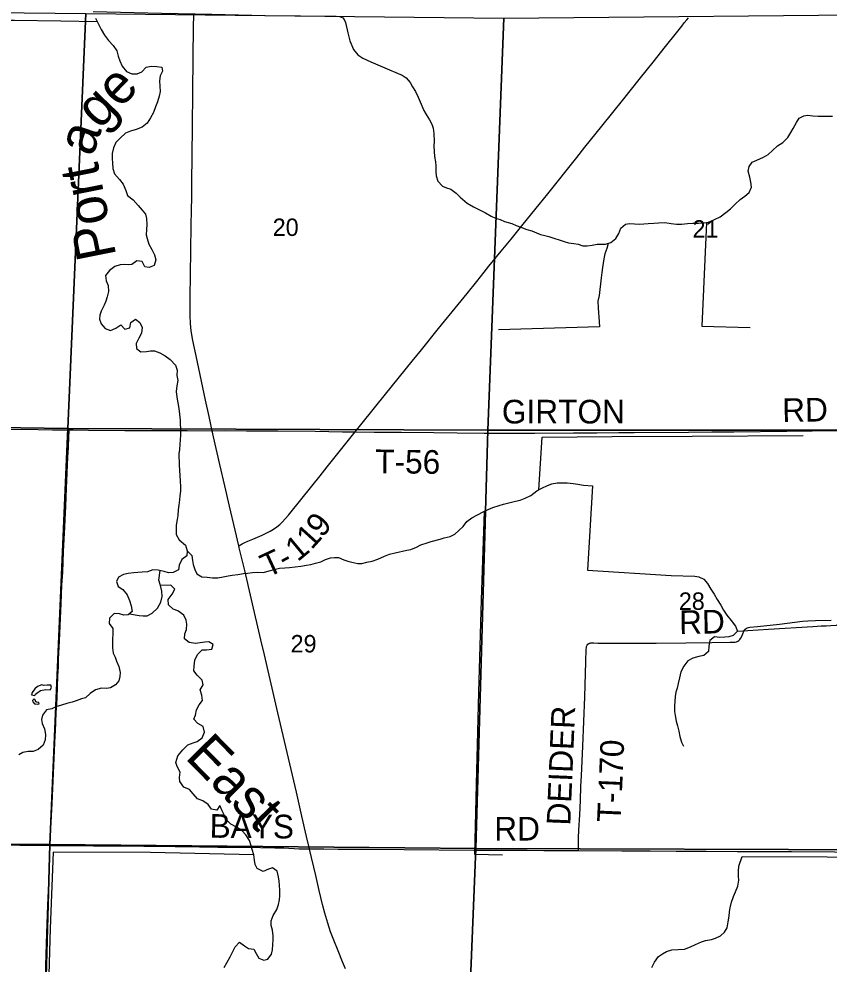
# Model space of a CAD drawing. Extents: x 1443599 to 1910620, y 1028088 to 1361369.
# Drawn here: x 1688678 to 1698953, y 1190596 to 1202581 of the extents above; entities that cross this region are included whole.
import ezdxf

# ---------------------------------------------------------------- set-up
doc = ezdxf.new("R2010")
doc.units = 0
for name, color, linetype in [('GM_X_Major_River', 7, 'Continuous'), ('GM_X_Major_River_Text', 7, 'Continuous'), ('GM_X_Minor_Lake', 7, 'Continuous'), ('GM_X_Minor_River', 7, 'Continuous'), ('GM_X_Section', 7, 'Continuous'), ('GM_X_Section_Text', 7, 'Continuous'), ('GM_X_State_Route', 7, 'Continuous'), ('GM_X_Township_Road', 7, 'Continuous'), ('GM_X_Township_Road_Text', 7, 'Continuous')]:
    doc.layers.add(name, color=color, linetype=linetype)

msp = doc.modelspace()

# ---------------------------------------------------------------- linework, layer by layer
at = {"layer": 'GM_X_Major_River'}
for points in [[(1689649, 1202592), (1689687, 1202516), (1689722, 1202449), (1689765, 1202376), (1689812, 1202309), (1689873, 1202243), (1689918, 1202178), (1689937, 1202110), (1689958, 1202051), (1689989, 1201983), (1690042, 1201914), (1690111, 1201886), (1690178, 1201885), (1690238, 1201910), (1690292, 1201969), (1690354, 1201982), (1690426, 1201977), (1690492, 1201970), (1690501, 1201919), (1690470, 1201858), (1690461, 1201796), (1690466, 1201727), (1690469, 1201661), (1690455, 1201601), (1690434, 1201531), (1690411, 1201466), (1690383, 1201394), (1690348, 1201328), (1690303, 1201261), (1690242, 1201208), (1690165, 1201181), (1690094, 1201158), (1690030, 1201134), (1689962, 1201071), (1689905, 1201013), (1689876, 1200948), (1689860, 1200876), (1689861, 1200808), (1689864, 1200755), (1689869, 1200685), (1689892, 1200615), (1689953, 1200543), (1690002, 1200484), (1690033, 1200407), (1690057, 1200341), (1690125, 1200285), (1690192, 1200216), (1690241, 1200155), (1690282, 1200104), (1690297, 1200050), (1690302, 1199975), (1690298, 1199911), (1690293, 1199845), (1690304, 1199795), (1690327, 1199724), (1690362, 1199659), (1690397, 1199591), (1690416, 1199526), (1690393, 1199454), (1690330, 1199429), (1690276, 1199438), (1690241, 1199503), (1690175, 1199512), (1690112, 1199465), (1690062, 1199462), (1690012, 1199467), (1689961, 1199464), (1689893, 1199441), (1689826, 1199392), (1689776, 1199327), (1689785, 1199261), (1689808, 1199202), (1689813, 1199124), (1689799, 1199056), (1689780, 1199004), (1689759, 1198952), (1689722, 1198877), (1689705, 1198825), (1689700, 1198775), (1689721, 1198714), (1689770, 1198657), (1689840, 1198632), (1689905, 1198659), (1689972, 1198704), (1690021, 1198649), (1690083, 1198662), (1690099, 1198730), (1690158, 1198773)], [(1690158, 1198773), (1690213, 1198731), (1690242, 1198667), (1690231, 1198597), (1690197, 1198535), (1690166, 1198466), (1690169, 1198401), (1690226, 1198360), (1690295, 1198363), (1690345, 1198372), (1690397, 1198371), (1690467, 1198346), (1690532, 1198311), (1690598, 1198263), (1690663, 1198192), (1690686, 1198129), (1690680, 1198059), (1690693, 1197995), (1690680, 1197927), (1690673, 1197857), (1690681, 1197784), (1690694, 1197714), (1690705, 1197642), (1690716, 1197571), (1690724, 1197495), (1690725, 1197443), (1690726, 1197386), (1690727, 1197308), (1690724, 1197238), (1690719, 1197188), (1690714, 1197120), (1690707, 1197066), (1690712, 1196925), (1690713, 1196853), (1690718, 1196791), (1690722, 1196721), (1690729, 1196650), (1690726, 1196594), (1690717, 1196532), (1690714, 1196482), (1690705, 1196414), (1690698, 1196358), (1690693, 1196286), (1690686, 1196234), (1690674, 1196162), (1690673, 1196110), (1690674, 1196044), (1690709, 1195977), (1690792, 1195906), (1690813, 1195836)], [(1690813, 1195836), (1690808, 1195774), (1690743, 1195725), (1690711, 1195656), (1690700, 1195596), (1690635, 1195561), (1690573, 1195558), (1690521, 1195573), (1690445, 1195592), (1690375, 1195594), (1690310, 1195571), (1690242, 1195564), (1690186, 1195563), (1690136, 1195556), (1690065, 1195549), (1690005, 1195538), (1689940, 1195501), (1689917, 1195449), (1689936, 1195385), (1689997, 1195346), (1690050, 1195277), (1690079, 1195206), (1690100, 1195137), (1690113, 1195069), (1690062, 1195024), (1690008, 1195021), (1689954, 1195036), (1689884, 1195043), (1689826, 1194982), (1689823, 1194916), (1689870, 1194853), (1689869, 1194784), (1689866, 1194716), (1689863, 1194660), (1689866, 1194608), (1689874, 1194538)], [(1690079, 1195038), (1690202, 1195015), (1690252, 1195012), (1690306, 1195011), (1690369, 1195044), (1690437, 1195109), (1690476, 1195185), (1690493, 1195257), (1690489, 1195323), (1690474, 1195395), (1690453, 1195466), (1690470, 1195586)], [(1691701, 1191807), (1691676, 1191860), (1691665, 1191912), (1691656, 1191982), (1691637, 1192047), (1691624, 1192097), (1691603, 1192162), (1691557, 1192233), (1691503, 1192290), (1691436, 1192333), (1691366, 1192371), (1691313, 1192420), (1691288, 1192472), (1691257, 1192541), (1691224, 1192606), (1691187, 1192548), (1691121, 1192560), (1691080, 1192620), (1691012, 1192664), (1690943, 1192691), (1690886, 1192756), (1690843, 1192809), (1690771, 1192841), (1690718, 1192912), (1690715, 1192962), (1690722, 1193030), (1690687, 1193101), (1690666, 1193153), (1690694, 1193235), (1690755, 1193312), (1690821, 1193377), (1690887, 1193402), (1690938, 1193419), (1691001, 1193464), (1691030, 1193536), (1691013, 1193608), (1690946, 1193648), (1690895, 1193701), (1690916, 1193753), (1690931, 1193819), (1690966, 1193882), (1691007, 1193938), (1690999, 1194006), (1690978, 1194074), (1691015, 1194136), (1691002, 1194198), (1690937, 1194260), (1690898, 1194315), (1690899, 1194375), (1690910, 1194451), (1690944, 1194522), (1691003, 1194579), (1691059, 1194580), (1691125, 1194589), (1691141, 1194649), (1691087, 1194682), (1691035, 1194679), (1690978, 1194670), (1690916, 1194663), (1690836, 1194673), (1690777, 1194720), (1690782, 1194784), (1690805, 1194840), (1690808, 1194906), (1690801, 1194958), (1690768, 1195019), (1690693, 1195074), (1690633, 1195098), (1690574, 1195153), (1690569, 1195219), (1690622, 1195286), (1690656, 1195352), (1690604, 1195399), (1690474, 1195395)], [(1689874, 1194538), (1689898, 1194487), (1689917, 1194436), (1689946, 1194368), (1689962, 1194293), (1689957, 1194243), (1689944, 1194189), (1689903, 1194138), (1689839, 1194101), (1689788, 1194090), (1689724, 1194093), (1689651, 1194074), (1689580, 1194025), (1689521, 1193972), (1689471, 1193961), (1689404, 1193932), (1689354, 1193917), (1689287, 1193900), (1689217, 1193881), (1689146, 1193857), (1689095, 1193831), (1689027, 1193819), (1688977, 1193751), (1688964, 1193697), (1688974, 1193647), (1689002, 1193578), (1689015, 1193508), (1689012, 1193440), (1688985, 1193370), (1688924, 1193317), (1688857, 1193292), (1688795, 1193291), (1688726, 1193280), (1688676, 1193251)], [(1691283, 1190553), (1691321, 1190622), (1691358, 1190686), (1691394, 1190762), (1691421, 1190813), (1691476, 1190872), (1691539, 1190829), (1691591, 1190794), (1691659, 1190787), (1691686, 1190732), (1691719, 1190671), (1691783, 1190646), (1691833, 1190657), (1691880, 1190721), (1691893, 1190777), (1691899, 1190845), (1691902, 1190903), (1691903, 1190953), (1691892, 1191025), (1691879, 1191084), (1691876, 1191146), (1691903, 1191214), (1691947, 1191289), (1691972, 1191353), (1691981, 1191409), (1691986, 1191463), (1691989, 1191529), (1691984, 1191595), (1691977, 1191646), (1691968, 1191704), (1691954, 1191774), (1691894, 1191818), (1691844, 1191798), (1691775, 1191772), (1691701, 1191807)]]:
    msp.add_lwpolyline(points, dxfattribs=at)
at = {"layer": 'GM_X_Minor_Lake'}
for p, q in [((1688996, 1194128), (1688968, 1194137)), ((1688874, 1193896), (1688888, 1193895))]:
    msp.add_line(p, q, dxfattribs=at)
for points in [[(1688968, 1194137), (1688914, 1194114), (1688881, 1194086), (1688848, 1194038), (1688838, 1194011), (1688880, 1194002), (1688890, 1194018), (1688906, 1194033), (1688951, 1194067), (1689019, 1194076), (1689074, 1194075), (1689092, 1194102), (1689081, 1194133), (1689037, 1194131), (1688996, 1194128)], [(1688888, 1193895), (1688914, 1193893), (1688936, 1193894), (1688930, 1193915), (1688904, 1193919), (1688894, 1193923), (1688885, 1193946), (1688873, 1193958), (1688852, 1193938), (1688854, 1193920), (1688874, 1193896)]]:
    msp.add_lwpolyline(points, dxfattribs=at)
at = {"layer": 'GM_X_Minor_River'}
for points in [[(1689618, 1202675), (1690487, 1202655), (1691124, 1202642), (1691800, 1202625), (1692702, 1202615), (1692745, 1202610), (1692786, 1202595), (1692802, 1202575), (1692821, 1202535), (1692849, 1202404), (1692875, 1202305), (1692923, 1202192), (1692976, 1202127), (1693039, 1202083), (1693141, 1202037), (1693348, 1201947), (1693489, 1201887), (1693537, 1201866), (1693587, 1201833)], [(1689672, 1202546), (1689211, 1202552), (1688623, 1202561), (1688118, 1202562), (1687412, 1202577), (1686863, 1202577), (1686812, 1201569), (1686787, 1200886), (1686768, 1200303), (1686738, 1199647), (1686720, 1199014), (1686707, 1198527), (1686694, 1197925), (1686666, 1197314), (1686650, 1196683)], [(1693587, 1201833), (1693640, 1201774), (1693669, 1201722), (1693706, 1201661), (1693741, 1201588), (1693766, 1201528), (1693813, 1201419), (1693844, 1201368), (1693887, 1201301), (1693914, 1201247), (1693930, 1201196), (1693941, 1201130), (1693943, 1201026), (1693942, 1200970), (1693945, 1200901), (1693948, 1200835), (1693959, 1200769), (1693964, 1200719), (1693967, 1200646), (1693968, 1200590), (1693989, 1200524), (1694048, 1200461), (1694102, 1200438), (1694154, 1200423), (1694222, 1200372), (1694273, 1200319), (1694362, 1200245), (1694441, 1200200), (1694519, 1200161), (1694597, 1200121), (1694666, 1200080), (1694724, 1200055), (1694780, 1200038), (1694838, 1200013), (1694931, 1199986), (1694985, 1199963), (1695045, 1199942), (1695119, 1199911), (1695183, 1199896), (1695242, 1199869), (1695294, 1199848), (1695346, 1199833), (1695400, 1199822), (1695462, 1199801), (1695540, 1199774), (1695592, 1199759), (1695648, 1199742), (1695716, 1199733), (1695772, 1199726), (1695829, 1199703), (1695884, 1199702), (1695950, 1199711), (1696012, 1199724), (1696064, 1199724), (1696117, 1199727), (1696183, 1199744), (1696248, 1199797), (1696287, 1199862), (1696310, 1199928), (1696369, 1199977), (1696423, 1199985), (1696486, 1199982), (1696550, 1199977), (1696604, 1199982), (1696660, 1199987), (1696730, 1199990), (1696791, 1199995), (1696871, 1199998), (1696951, 1199988), (1697019, 1199979), (1697079, 1199980), (1697155, 1199985), (1697224, 1199990), (1697298, 1199991), (1697368, 1199996), (1697422, 1200005), (1697501, 1200038), (1697572, 1200071), (1697645, 1200126), (1697704, 1200173), (1697763, 1200234), (1697826, 1200290), (1697883, 1200333), (1697938, 1200380), (1697969, 1200448), (1697962, 1200512), (1697949, 1200576), (1697928, 1200649), (1697937, 1200711), (1697976, 1200764), (1698036, 1200792), (1698119, 1200826), (1698182, 1200862), (1698235, 1200911), (1698300, 1200970), (1698365, 1201013), (1698430, 1201078), (1698469, 1201142), (1698498, 1201193), (1698539, 1201269), (1698574, 1201323)], [(1698574, 1201323), (1698633, 1201354), (1698683, 1201359), (1698747, 1201354), (1698813, 1201349), (1698879, 1201347), (1698942, 1201349), (1698995, 1201347)], [(1697399, 1200001), (1697340, 1198687), (1697951, 1198670)], [(1696151, 1199735), (1696134, 1199670), (1696109, 1199603), (1696094, 1199541), (1696087, 1199485), (1696080, 1199427), (1696071, 1199367), (1696062, 1199298), (1696053, 1199224), (1696045, 1199150), (1696036, 1199076), (1696019, 1199004), (1696022, 1198918), (1696027, 1198856), (1696034, 1198804), (1696039, 1198675)], [(1696039, 1198675), (1694760, 1198639)], [(1695271, 1196611), (1695312, 1197277), (1696203, 1197285), (1697218, 1197289), (1698624, 1197300)], [(1693448, 1195809), (1693596, 1195844), (1693650, 1195855), (1693719, 1195882), (1693775, 1195911), (1693856, 1195938), (1693908, 1195955), (1694021, 1195986), (1694073, 1195999), (1694146, 1196020), (1694206, 1196049), (1694259, 1196092), (1694312, 1196146), (1694357, 1196207), (1694422, 1196254), (1694493, 1196291), (1694566, 1196330), (1694628, 1196359), (1694687, 1196384), (1694768, 1196413), (1694824, 1196426), (1694907, 1196449), (1694975, 1196466), (1695033, 1196479), (1695098, 1196504), (1695169, 1196537), (1695246, 1196598), (1695310, 1196631), (1695383, 1196666), (1695438, 1196684), (1695506, 1196697), (1695562, 1196698), (1695632, 1196697), (1695706, 1196691), (1695766, 1196680), (1695840, 1196669), (1695953, 1196661)], [(1695953, 1196661), (1695890, 1195590), (1696950, 1195525), (1697248, 1195514)], [(1694580, 1196337), (1694542, 1195216), (1694508, 1194043), (1694476, 1192879), (1694454, 1191991), (1694811, 1191981)], [(1690813, 1195836), (1690870, 1195777), (1690881, 1195713), (1690888, 1195663), (1690907, 1195598), (1690936, 1195546), (1690997, 1195506), (1691065, 1195501), (1691131, 1195492), (1691202, 1195493), (1691268, 1195507), (1691330, 1195518), (1691383, 1195527), (1691453, 1195538), (1691526, 1195549), (1691576, 1195552), (1691640, 1195561), (1691708, 1195564), (1691779, 1195562), (1691851, 1195581), (1691914, 1195600), (1691984, 1195615), (1692052, 1195621), (1692111, 1195626), (1692183, 1195635), (1692253, 1195642), (1692326, 1195653), (1692380, 1195664), (1692439, 1195681), (1692505, 1195697), (1692568, 1195728), (1692629, 1195749), (1692681, 1195752), (1692733, 1195751), (1692797, 1195724), (1692850, 1195705), (1692902, 1195692), (1692974, 1195677), (1693026, 1195676), (1693091, 1195691), (1693159, 1195706), (1693228, 1195732), (1693313, 1195767), (1693377, 1195792), (1693448, 1195809)], [(1697248, 1195514), (1697300, 1195506), (1697362, 1195477), (1697409, 1195420), (1697452, 1195349), (1697495, 1195286), (1697534, 1195221), (1697579, 1195148), (1697612, 1195084), (1697654, 1195019), (1697711, 1194952), (1697766, 1194883), (1697791, 1194818), (1697736, 1194761), (1697679, 1194746), (1697629, 1194741), (1697569, 1194738), (1697501, 1194745), (1697442, 1194701), (1697429, 1194629), (1697424, 1194559), (1697365, 1194508), (1697301, 1194497), (1697226, 1194476), (1697163, 1194441), (1697112, 1194374), (1697073, 1194300), (1697054, 1194224), (1697037, 1194152), (1697026, 1194096), (1697011, 1194042), (1697002, 1193990), (1696997, 1193926), (1696992, 1193870), (1696993, 1193798), (1697002, 1193748), (1697013, 1193677), (1697028, 1193617), (1697045, 1193549), (1697060, 1193482), (1697081, 1193412), (1697108, 1193361)], [(1698746, 1194878), (1698802, 1194881), (1698853, 1194885), (1698915, 1194885), (1698975, 1194888), (1699047, 1194893), (1699120, 1194922), (1699187, 1194977), (1699228, 1195041), (1699243, 1195112), (1699312, 1195139), (1699384, 1195150), (1699446, 1195147), (1699507, 1195148), (1699559, 1195162), (1699615, 1195175), (1699665, 1195184), (1699734, 1195197)], [(1697791, 1194818), (1698186, 1194842), (1698746, 1194878)], [(1691656, 1191982), (1690348, 1192010), (1689111, 1192013), (1689073, 1191047), (1689055, 1190315), (1689024, 1189381), (1689004, 1188294), (1688989, 1187422)], [(1696706, 1190552), (1696739, 1190620), (1696790, 1190693), (1696841, 1190727), (1696891, 1190756), (1696960, 1190777), (1697117, 1190786), (1697193, 1190813), (1697260, 1190846), (1697333, 1190877), (1697387, 1190893), (1697461, 1190909), (1697512, 1190923), (1697576, 1190956), (1697627, 1191001), (1697658, 1191055), (1697673, 1191131), (1697685, 1191205), (1697689, 1191257), (1697696, 1191311), (1697713, 1191383), (1697739, 1191453), (1697765, 1191510), (1697795, 1191586), (1697810, 1191660), (1697805, 1191710), (1697802, 1191776), (1697809, 1191838), (1697851, 1191960)], [(1697851, 1191960), (1700006, 1191953), (1702413, 1191955), (1702411, 1191334), (1702395, 1190686), (1703522, 1190675), (1704942, 1190679)]]:
    msp.add_lwpolyline(points, dxfattribs=at)
at = {"layer": 'GM_X_Section'}
for points in [[(1684061, 1202709), (1689528, 1202650), (1689300, 1197389), (1683913, 1197462)], [(1689528, 1202650), (1694826, 1202591), (1694624, 1197366), (1689300, 1197389)], [(1694826, 1202591), (1700149, 1202640), (1699955, 1197367), (1694624, 1197366)], [(1689300, 1197389), (1689070, 1192111), (1683747, 1192150), (1683913, 1197462)], [(1694624, 1197366), (1694474, 1192060), (1689070, 1192111), (1689300, 1197389)], [(1694624, 1197366), (1699955, 1197367), (1699762, 1192045), (1694474, 1192060)], [(1683747, 1192150), (1689070, 1192111), (1688920, 1186781), (1683672, 1186813)], [(1689070, 1192111), (1694474, 1192060), (1694259, 1186758), (1689188, 1186776), (1688920, 1186781)], [(1694474, 1192060), (1699762, 1192045), (1699547, 1186749), (1694377, 1186759), (1694259, 1186758)]]:
    msp.add_lwpolyline(points, close=True, dxfattribs=at)
at = {"layer": 'GM_X_State_Route'}
for points in [[(1691130, 1197359), (1691090, 1197539), (1691045, 1197748), (1690924, 1198309), (1690885, 1198502), (1690867, 1198599), (1690858, 1198664), (1690853, 1198729), (1690851, 1198811), (1690851, 1198942), (1690851, 1199057), (1690854, 1199336), (1690864, 1199960), (1690866, 1200157), (1690869, 1200321), (1690871, 1200501), (1690879, 1201207), (1690885, 1201667), (1690894, 1202488), (1690898, 1202619), (1690898, 1202623)], [(1695277, 1200230), (1695385, 1200363), (1695754, 1200824), (1695856, 1200953), (1696072, 1201221), (1696349, 1201568), (1696544, 1201811), (1696740, 1202054), (1696861, 1202209), (1697035, 1202427), (1697086, 1202491), (1697116, 1202530), (1697147, 1202568), (1697169, 1202593)], [(1693666, 1198243), (1693782, 1198386), (1693999, 1198654), (1694247, 1198961), (1694361, 1199101), (1694486, 1199253), (1694578, 1199368), (1694639, 1199446), (1694795, 1199636), (1694919, 1199790), (1695074, 1199980), (1695277, 1200230)], [(1691569, 1197357), (1691960, 1197357), (1692436, 1197353), (1692781, 1197346), (1692942, 1197347), (1693029, 1197454), (1693329, 1197824), (1693666, 1198243)], [(1688281, 1197378), (1688922, 1197373), (1689102, 1197372), (1689318, 1197370), (1689365, 1197370), (1689562, 1197368), (1690022, 1197364), (1690531, 1197364), (1690570, 1197363)], [(1690570, 1197363), (1690810, 1197360), (1691130, 1197359)], [(1691130, 1197359), (1691139, 1197359), (1691303, 1197361), (1691566, 1197357), (1691569, 1197357)], [(1692820, 1190534), (1692783, 1190625), (1692726, 1190762), (1692671, 1190899), (1692631, 1191006), (1692595, 1191115), (1692558, 1191241), (1692529, 1191352), (1692487, 1191528), (1692442, 1191719), (1692365, 1192055), (1692364, 1192057), (1692327, 1192215), (1692268, 1192471), (1692198, 1192775), (1692096, 1193206), (1691963, 1193782), (1691851, 1194261), (1691791, 1194517), (1691746, 1194709), (1691627, 1195221), (1691541, 1195588), (1691473, 1195876), (1691467, 1195899), (1691421, 1196099), (1691350, 1196403), (1691291, 1196659), (1691228, 1196931), (1691147, 1197283), (1691130, 1197359)]]:
    msp.add_lwpolyline(points, dxfattribs=at)
at = {"layer": 'GM_X_Township_Road'}
for points in [[(1689168, 1194116), (1689168, 1194117), (1689173, 1194248), (1689178, 1194364), (1689182, 1194463), (1689192, 1194693), (1689213, 1195170), (1689224, 1195399), (1689233, 1195564), (1689245, 1195827), (1689259, 1196139), (1689272, 1196402), (1689281, 1196632), (1689300, 1197026), (1689306, 1197141), (1689313, 1197287), (1689317, 1197349), (1689318, 1197370)], [(1692942, 1197347), (1693185, 1197342), (1693529, 1197339), (1693940, 1197335), (1694235, 1197331), (1694579, 1197328), (1695219, 1197330), (1695711, 1197331), (1696007, 1197333), (1696285, 1197335), (1696482, 1197336), (1697171, 1197341), (1697467, 1197344), (1697745, 1197346), (1698418, 1197353), (1699058, 1197360), (1699452, 1197365), (1699796, 1197367), (1699942, 1197367)], [(1691467, 1195899), (1691508, 1195924), (1691541, 1195941), (1691579, 1195959), (1691643, 1195986), (1691763, 1196036), (1691823, 1196064), (1691866, 1196087), (1691907, 1196112), (1691947, 1196141), (1691985, 1196172), (1692020, 1196205), (1692053, 1196241), (1692096, 1196290), (1692271, 1196506), (1692497, 1196787), (1692589, 1196902), (1692721, 1197069), (1692942, 1197347)], [(1696356, 1194666), (1696760, 1194667), (1697137, 1194669), (1697466, 1194674), (1697696, 1194677), (1697745, 1194678), (1697761, 1194679), (1697778, 1194683), (1697794, 1194691), (1697807, 1194699), (1697820, 1194711), (1697831, 1194725), (1697840, 1194741), (1697846, 1194755), (1697857, 1194785), (1697870, 1194816), (1697877, 1194831), (1697887, 1194843), (1697900, 1194853), (1697915, 1194860), (1697930, 1194865), (1697947, 1194868), (1698045, 1194878), (1698322, 1194907), (1698616, 1194944), (1698681, 1194949), (1698780, 1194952), (1698977, 1194958)], [(1695773, 1192035), (1695774, 1192129), (1695775, 1192195), (1695779, 1192293), (1695790, 1192490), (1695798, 1192671), (1695805, 1192851), (1695811, 1192982), (1695828, 1193360), (1695853, 1193983), (1695869, 1194427), (1695872, 1194591), (1695874, 1194608), (1695878, 1194623), (1695885, 1194638), (1695894, 1194651), (1695907, 1194661), (1695914, 1194664), (1695922, 1194667), (1695930, 1194668), (1695939, 1194669), (1695955, 1194669), (1695971, 1194668), (1696020, 1194667), (1696168, 1194666), (1696333, 1194665), (1696356, 1194666)], [(1689138, 1193490), (1689141, 1193550), (1689151, 1193780), (1689158, 1193900), (1689162, 1193970), (1689168, 1194116)], [(1689073, 1192101), (1689084, 1192320), (1689100, 1192632), (1689124, 1193206), (1689133, 1193403), (1689138, 1193490)], [(1686943, 1192126), (1686981, 1192126), (1687211, 1192123), (1687572, 1192119), (1688048, 1192112), (1688409, 1192107), (1688688, 1192105), (1688967, 1192102), (1689073, 1192101)], [(1688935, 1187301), (1688934, 1187325), (1688934, 1187383), (1688937, 1187565), (1688943, 1187892), (1688949, 1188155), (1688953, 1188402), (1688958, 1188599), (1688967, 1188813), (1688977, 1189207), (1688989, 1189536), (1688999, 1189831), (1689011, 1190275), (1689025, 1190719), (1689034, 1190982), (1689046, 1191343), (1689056, 1191622), (1689069, 1192000), (1689072, 1192082), (1689073, 1192101)], [(1689073, 1192101), (1689296, 1192099), (1689624, 1192097), (1690264, 1192091), (1690658, 1192085), (1690970, 1192081), (1690975, 1192081)], [(1690975, 1192081), (1691200, 1192079), (1691498, 1192077)], [(1691498, 1192077), (1691561, 1192077), (1691922, 1192071), (1692037, 1192068), (1692234, 1192059), (1692349, 1192057), (1692364, 1192057)], [(1692364, 1192057), (1692546, 1192057), (1692726, 1192055), (1693120, 1192052), (1693564, 1192049), (1694449, 1192042), (1694450, 1192042), (1694664, 1192041), (1695123, 1192039), (1695337, 1192038), (1695649, 1192036), (1695773, 1192035)], [(1695773, 1192035), (1696323, 1192032), (1696685, 1192032), (1697014, 1192028), (1697145, 1192027), (1697392, 1192027), (1697787, 1192024), (1698099, 1192023), (1698477, 1192022), (1699020, 1192018), (1699365, 1192016), (1699661, 1192015), (1699747, 1192015)]]:
    msp.add_lwpolyline(points, dxfattribs=at)

# ---------------------------------------------------------------- texts
at = {"layer": 'GM_X_Major_River_Text'}
for s, height, rotation, p in [('ge', 500.3, 46.2354, (1689704, 1201167)), ('a', 500, 71.2343, (1689612, 1200824)), ('Port', 500.3, 101.2326, (1689915, 1199576)), ('East', 500.3, 314.5157, (1690773, 1193212))]:
    msp.add_text(s, height=height, rotation=rotation, dxfattribs=at).set_placement(p)
at = {"layer": 'GM_X_Section_Text'}
for s, p in [('20', (1691897, 1199829)), ('21', (1697221, 1199808)), ('28', (1697047, 1195088)), ('29', (1692124, 1194548))]:
    msp.add_text(s, height=221, rotation=0, dxfattribs=at).set_placement(p)
at = {"layer": 'GM_X_Township_Road_Text'}
for s, rotation, p in [('GIRTON', 0, (1694803, 1197451)), ('RD', 0.9824, (1698360, 1197469)), ('T-56', 359.2939, (1693195, 1196822)), ('9', 50.9471, (1692524, 1195991)), ('1', 47.8438, (1692389, 1195841)), ('1', 39.6758, (1692213, 1195690)), ('T', 24.9281, (1691830, 1195492)), ('-', 28.7309, (1692053, 1195596)), ('RD', 0.9742, (1697053, 1194781)), ('DEIDER', 87.5829, (1695670, 1192349)), ('T-170', 87.4737, (1696309, 1192389)), ('BAYS', 359.483, (1691095, 1192198)), ('RD', 0, (1694706, 1192163))]:
    msp.add_text(s, height=300, rotation=rotation, dxfattribs=at).set_placement(p)

doc.saveas('drawing.dxf')
